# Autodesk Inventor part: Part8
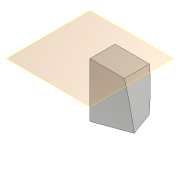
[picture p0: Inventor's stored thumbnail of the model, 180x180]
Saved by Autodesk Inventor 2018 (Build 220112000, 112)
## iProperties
Created: 2015-07
Part Number: Part8
Material: Generic
Document SubType Name: Modeling
Designer: Sandeep
Density: 1 g/cm^3
Appearance: Default
Author: Sandeep
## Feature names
1. Sweep1
## Parameters: d0 = 0, d1 = -20 deg
